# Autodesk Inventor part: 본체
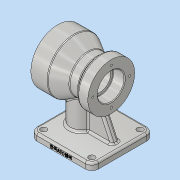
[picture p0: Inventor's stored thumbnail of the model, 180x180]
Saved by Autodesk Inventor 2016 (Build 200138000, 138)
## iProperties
Created: 2019-01
Part Number: 본체
Material: 알루미늄 6061
Document SubType Name: Modeling
Designer: Administrator
Mass: 898.816 g
Surface Area: 600.964 cm^2
Volume: 332.895 cm^3
Density: 2.7 g/cm^3
Appearance: 알루미늄 - 평지
Author: Administrator
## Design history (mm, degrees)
sketch "스케치1"
  geometry: L1 (-46, 46)-(46, 46); L2 (46, 46)-(46, -46); L3 (46, -46)-(-46, -46); L4 (-46, -46)-(-46, 46); L5 (-46, 46)-(46, -46); L6 (46, 46)-(-46, -46); 1 further point
  constraints: 12 end point, 2 midpoint, 2 parallel, 1 horizontal, 1 perpendicular
  dimensions: "d0" = 92 distance of L2.end L3.end; "d1" = 92 distance of L1.end L2.end
extrude "돌출1" new body sketch "스케치1" distance "d2" = 10; taper "d3" = 0 deg
fillet "모깎기1" dims "d4" = 10
sketch "스케치2"
  geometry: L1 (-36, -46)-(36, -46) reference; L2 (46, -36)-(46, 36) reference; L3 (36, 46)-(-36, 46) reference; L4 (-46, 36)-(-46, -36) reference; A1 r 10 centre (-36, -36) between (-46, -36) and (-36, -46) reference; A2 r 10 centre (36, -36) between (36, -46) and (46, -36) reference; A3 r 10 centre (36, 36) between (46, 36) and (36, 46) reference; A4 r 10 centre (-36, 36) between (-36, 46) and (-46, 36) reference; 5 further points
  constraints: 4 coincident
hole "구멍1" sketch "스케치2" at (-36, 36), (36, 36), (36, -36), (-36, -36) diameter "d5" = 9; stored, may be unused: countersink angle "d9" = 90 deg, drill point angle "d11" = 118 deg; dims "d6" = 6, "d7" = 4, "d8" = 2, "d10" = 8
sketch "스케치3"
  geometry: L1 (-36, -46)-(36, -46) reference; L2 (46, -36)-(46, 36) reference; L3 (36, 46)-(-36, 46) reference; L4 (-46, 36)-(-46, -36) reference; C1 r 16 at (-16, 0); C2 r 4.5 at (36, -36) reference; C3 r 4.5 at (-36, 36) reference; C4 r 4.5 at (36, 36) reference; C5 r 4.5 at (-36, -36) reference; A1 r 10 centre (-36, -36) between (-46, -36) and (-36, -46) reference; A2 r 10 centre (36, -36) between (36, -46) and (46, -36) reference; A3 r 10 centre (36, 36) between (46, 36) and (36, 46) reference; A4 r 10 centre (-36, 36) between (-36, 46) and (-46, 36) reference; 1 further point
  constraints: 1 centre point, 1 horizontal alignment
  dimensions: "d12" = 16 radius of C1; "d13" = 30 distance from line of C1.centre L4
extrude "돌출2" join sketch "스케치3" distance "d14" = 70; taper "d15" = 0 deg
sketch "스케치4"
  geometry: L1 (76.466, 80)-(-77.313, 80); L2 (51, 80)-(51, 120); L3 (51, 120)-(26, 120); L4 (26, 120)-(5.215, 108); L5 (5.215, 108)-(-8.126, 108); L6 (-8.126, 108)-(-14, 115); L7 (-14, 115)-(-29, 115); L8 (-29, 115)-(-29, 80); L9 (46, 0)-(46, 10) reference; 1 further point
  constraints: 16 end point, 2 parallel, 2 point on line, 2 vertical, 1 horizontal, 1 perpendicular
  dimensions: "d16" = 80 distance from line of L1 point (0, 0); "d17" = 80 diameter of L3 L1; "d18" = 25 distance of L2.end L3.end; "d19" = 30 deg angle of L5 L4; "d20" = 50 deg angle of L6 L5; "d21" = 56 diameter of L5 L1; "d22" = 70 diameter of L7 L1; "d23" = 80 distance between parallel lines of L8 L2; "d24" = 15 distance of L6.end L7.end; "d25" = 5 distance between parallel lines of L9 L2
revolve "회전1" sketch "스케치4" stored, may be unused: angle "d26" = 90 deg
sketch "스케치5"
  geometry: C1 r 40 at (0, 0) reference; C2 r 26 at (0, 0); 1 further point
  constraints: 1 centre point, 1 coincident
  dimensions: "d27" = 26 radius of C2
extrude "돌출3" cut sketch "스케치5" distance "d28" = 20; taper "d29" = 0 deg
sketch "스케치6"
  geometry: C1 r 26 at (0, 0) reference; C2 r 16 at (0, 0); 1 further point
  constraints: 1 centre point, 1 coincident
  dimensions: "d30" = 16 radius of C2
sketch "스케치7"
  geometry: C1 r 35 at (0, 0) reference; C2 r 20 at (0, 0); 1 further point
  constraints: 1 centre point, 1 coincident
  dimensions: "d31" = 20 radius of C2
extrude "돌출4" cut sketch "스케치7" distance "d32" = 17; taper "d33" = 0 deg
extrude "돌출5" cut sketch "스케치6" stored distance "d34" = 17; taper "d35" = 0 deg
sketch "스케치8"
  geometry: C1 r 40 at (0, 0) reference; 2 further points
  constraints: 1 vertical alignment
  dimensions: "d36" = 33 distance of C1.centre point (0, 33)
hole "구멍2" sketch "스케치8" at (0, 33) diameter "d37" = 3.242; stored, may be unused: countersink angle "d41" = 90 deg, drill point angle "d43" = 118 deg; dims "d38" = 9, "d39" = 4, "d40" = 2, "d42" = 11
sketch "스케치9"
  geometry: C1 r 35 at (0, 0) reference; A1 r 28 centre (0, 0) between (25.383, 11.819) and (25.383, -11.819) reference; 2 further points
  constraints: 1 vertical alignment
  dimensions: "d47" = 27.5 distance of A1.centre point (0, -27.5)
hole "구멍3" sketch "스케치9" at (0, -27.5) diameter "d48" = 3.242; stored, may be unused: countersink angle "d52" = 90 deg, drill point angle "d54" = 118 deg; dims "d49" = 9, "d50" = 4, "d51" = 2, "d53" = 11
sketch "스케치10"
  geometry: L1 (0, 0)-(72, 0) reference; L2 (-10, 10)-(-10, 0) reference; 2 further points
  constraints: 1 other
  dimensions: "d58" = 4 distance from line of point (36, 4) L1; "d59" = 46 distance from line of L2 point (36, 4)
sketch "스케치11"
  geometry: L1 (-36, 10)-(36, 10) reference; L2 (-36, 10)-(-24.041, 35.646); L3 (-46, 10)-(-46, 0) reference; 1 further point
  constraints: 2 end point, 1 point on line
  dimensions: "d60" = 10 distance from line of L3 L2.start; "d61" = 25 deg angle of L3 L2
feature "리브1" sketch "스케치11" dims "d62" = 1, "d63" = 10, "d64" = 0, "d65" = 0, "d66" = 1, "d67" = 1
chamfer "모따기1" distance "d68" = 1; stored, may be unused: second distance "d69" = 2, angle "d70" = 45 deg
fillet "모깎기2" dims "d71" = 1
fillet "모깎기3" dims "d72" = 0.6
fillet "모깎기4" dims "d73" = 3
fillet "모깎기5" dims "d74" = 3
fillet "모깎기6" dims "d75" = 3
fillet "모깎기7" dims "d76" = 3
feature "엠보싱1" dims "d0" = 92, "d1" = 92, "d77" = 0.5, "d78" = 0
feature "분할1"
node "솔리드1"
pattern_circular "원형 패턴1" dims angle "d45" = 360 deg
pattern_circular "원형 패턴2" dims angle "d56" = 360 deg
node "투영된 루프1"
node "투영된 루프2"
